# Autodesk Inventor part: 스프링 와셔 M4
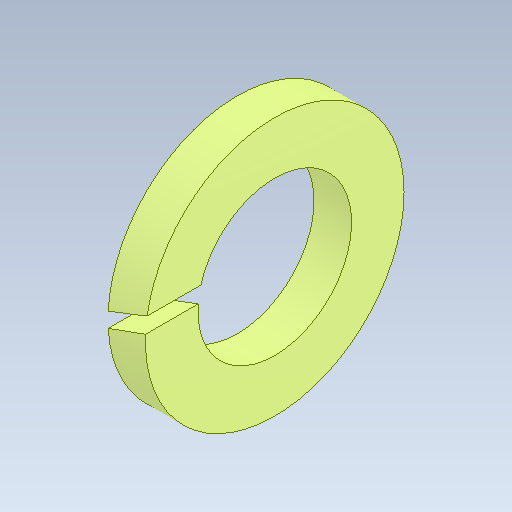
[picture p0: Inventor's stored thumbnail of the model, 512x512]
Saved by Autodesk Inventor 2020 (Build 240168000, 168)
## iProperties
Created: 2024-07
Part Number: 스프링 와셔 M4
Material: 강철, 연강
Description: 스프링 잠금 와셔
Document SubType Name: Modeling
Designer: oem
Density: 7.85 g/cm^3
Appearance: 기본값
Mass: 0.185479 g
Surface Area: 0.840057 cm^2
Volume: 0.023628 cm^3
Sending System: Autodesk Inventor 2025
Preprocessor: ST-DEVELOPER v20
Author: jhkim
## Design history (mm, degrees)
feature "Solid1"
node "솔리드1"
